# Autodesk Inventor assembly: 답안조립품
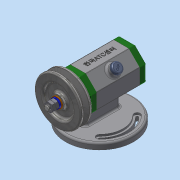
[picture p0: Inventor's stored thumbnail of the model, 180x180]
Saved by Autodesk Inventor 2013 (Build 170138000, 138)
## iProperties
Created: 2017-06
Part Number: 답안조립품
Document SubType Name: Assembly
Designer: Administrator
Author: Administrator
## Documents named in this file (14)
- C:\Users\Administrator\Desktop\470607V1012\답안조립품.iam
- C:\Users\Administrator\Desktop\470607V1012\본체.ipt
- C:\Users\Administrator\Desktop\470607V1012\공용부품\V벨트풀리.ipt
- C:\Users\Administrator\Desktop\470607V1012\공용부품\고무캡.ipt
- C:\Users\Administrator\Desktop\470607V1012\공용부품\너트 M 8.ipt
- C:\Users\Administrator\Desktop\470607V1012\공용부품\뒤커버.ipt
- C:\Users\Administrator\Desktop\470607V1012\공용부품\베어링 15 x 32 x 9.ipt
- C:\Users\Administrator\Desktop\470607V1012\공용부품\볼트 M4 x 12.ipt
- C:\Users\Administrator\Desktop\470607V1012\공용부품\스프링와셔 8.ipt
- C:\Users\Administrator\Desktop\470607V1012\공용부품\앞커버.ipt
- C:\Users\Administrator\Desktop\470607V1012\공용부품\오일 실 15 25 7.ipt
- C:\Users\Administrator\Desktop\470607V1012\공용부품\와셔 8x17.ipt
- C:\Users\Administrator\Desktop\470607V1012\공용부품\축.ipt
- C:\Users\Administrator\Desktop\470607V1012\공용부품\키 3 x 3 x 12.ipt
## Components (2 placed, 2 different names)
1. V벨트풀리:1
2. 고무캡:1
